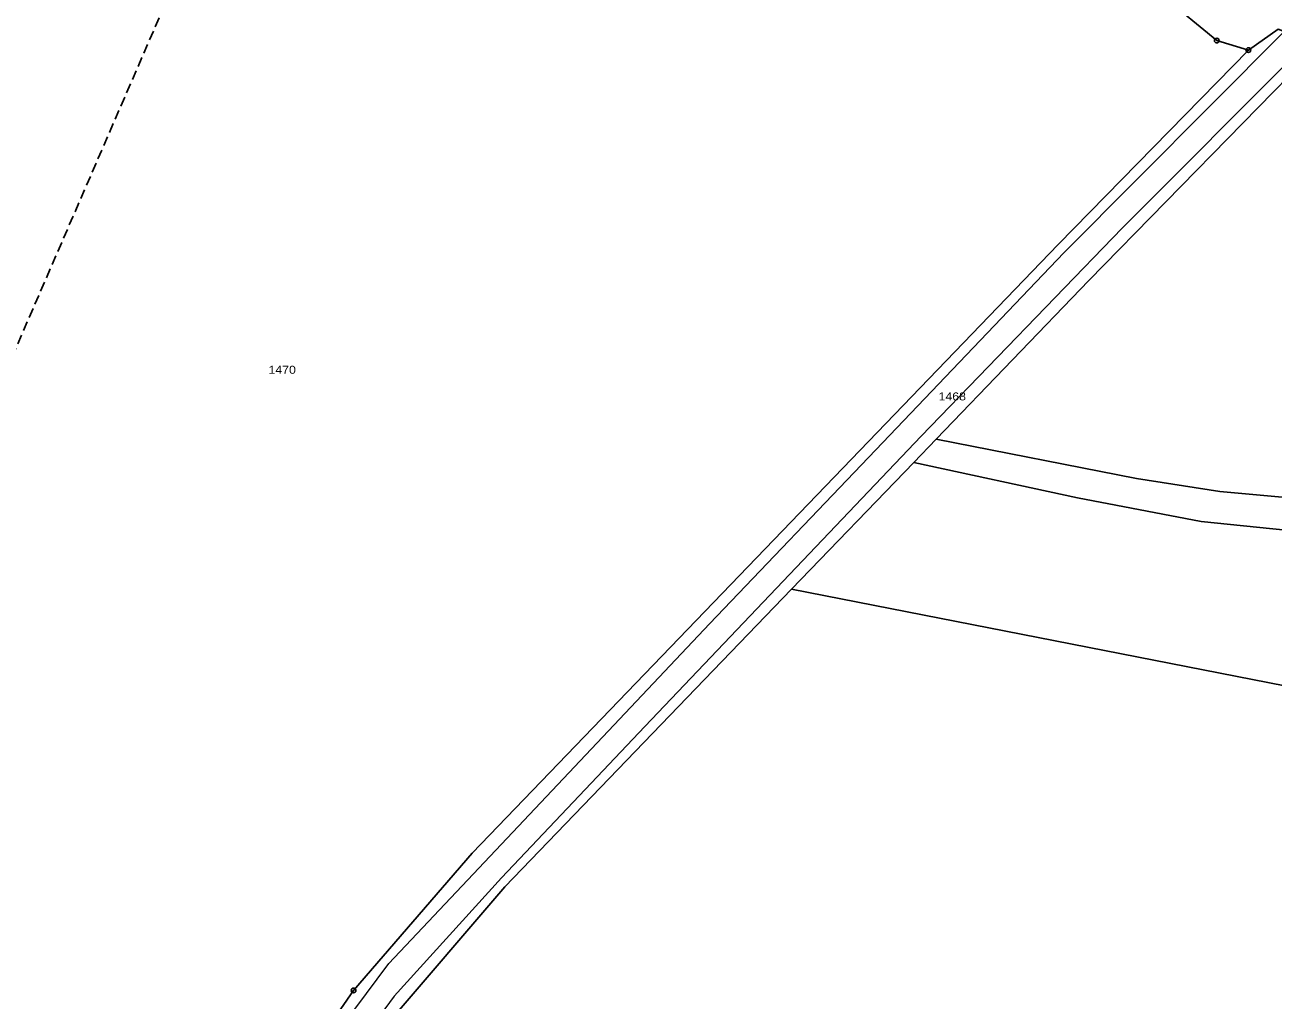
# Model space of a CAD drawing. Extents: x -872229 to -869198, y -1075981 to -1074329.
# Drawn here: x -871472.2 to -871207, y -1075594.7 to -1075387.5 of the extents above; entities that cross this region are included whole.
import ezdxf

# ---------------------------------------------------------------- set-up
doc = ezdxf.new("R2010")
doc.units = 0
doc.header["$LTSCALE"] = 0.68
doc.linetypes.add('MEDIUM_DASHED', pattern=[4.5, 3, -1.5])
for name, color, linetype, lineweight in [('1', 7, 'Continuous', 25), ('4', 7, 'Continuous', 13), ('6', 7, 'Continuous', 25), ('8', 7, 'Continuous', 25)]:
    doc.layers.add(name, color=color, linetype=linetype, lineweight=lineweight)
doc.layers.add('2', color=7, linetype='Continuous')

msp = doc.modelspace()

# ---------------------------------------------------------------- linework, layer by layer
at = {"layer": '1'}
for p, q in [((-871278.54, -1075475.47), (-871283.35, -1075480.46)), ((-871283.35, -1075480.46), (-871309.29, -1075507.4))]:
    msp.add_line(p, q, dxfattribs=at)
for points in [[(-871212.24, -1075392.84), (-871218.94, -1075390.82), (-871230.33, -1075381.38), (-871303.93, -1075360.22), (-871330.24, -1075349.97), (-871352.11, -1075340.43), (-871367.76, -1075336.32)], [(-871197.08, -1075391.62), (-871199.28, -1075390.81), (-871204.62, -1075388.86), (-871205.94, -1075388.38), (-871212.24, -1075392.84)], [(-871212.24, -1075392.84), (-871252.68, -1075434.13), (-871377.15, -1075563.45), (-871402.35, -1075592.63), (-871427.67, -1075629.24), (-871441.61, -1075657.13), (-871468.69, -1075704.44)], [(-871197.08, -1075391.62), (-871246.11, -1075441.8), (-871278.54, -1075475.47)], [(-871278.54, -1075475.47), (-871235.98, -1075483.88), (-871218.31, -1075486.6), (-871156.9, -1075492.22), (-871055.97, -1075499.77), (-870980.4, -1075505.56), (-870961.43, -1075507.47), (-870950.68, -1075443.64)], [(-870962.39, -1075513.2), (-870981.34, -1075511.21), (-871031.87, -1075507.16), (-871090.68, -1075503.32), (-871198.07, -1075495.44), (-871222.24, -1075493), (-871248.51, -1075487.96), (-871283.35, -1075480.46)], [(-871309.29, -1075507.4), (-871370.19, -1075570.62), (-871394.77, -1075599.26), (-871418.31, -1075635.76), (-871432.83, -1075664.02), (-871448.97, -1075707.84), (-871454.61, -1075721.79)], [(-870967.23, -1075543.73), (-871082, -1075537.03), (-871190.36, -1075530.7), (-871309.29, -1075507.4)]]:
    msp.add_lwpolyline(points, dxfattribs=at)
at = {"layer": '4'}
for p, q in [((-871199.28, -1075390.81), (-871239.07, -1075430.66)), ((-871394.86, -1075586.88), (-871326.72, -1075514.76)), ((-871340.49, -1075536.51), (-871370.95, -1075568.72))]:
    msp.add_line(p, q, dxfattribs=at)
for points in [[(-871326.72, -1075514.76), (-871291.4, -1075477.73), (-871251.44, -1075435.93), (-871204.62, -1075388.86)], [(-871239.07, -1075430.66), (-871281.77, -1075474.85), (-871340.49, -1075536.51)], [(-871370.95, -1075568.72), (-871393.73, -1075593.84), (-871411.43, -1075617.88), (-871422.7, -1075636.35)], [(-871423.61, -1075627.58), (-871411.59, -1075609.37), (-871394.86, -1075586.88)]]:
    msp.add_lwpolyline(points, dxfattribs=at)
at = {"layer": '6', "linetype": 'MEDIUM_DASHED'}
msp.add_lwpolyline([(-871440.02, -1075377.58), (-871476.16, -1075460.89), (-871517.14, -1075554.83)], dxfattribs=at)
at = {"layer": '8'}
for centre, radius in [((-871218.94, -1075390.8199), 0.5), ((-871218.94, -1075390.8199), 0.0303), ((-871212.24, -1075392.8399), 0.5), ((-871212.24, -1075392.8399), 0.0303), ((-871402.35, -1075592.6299), 0.5), ((-871402.35, -1075592.6299), 0.0303)]:
    msp.add_circle(centre, radius, dxfattribs=at)

# ---------------------------------------------------------------- texts
at = {"layer": '2', "width": 1.15}
for s, p in [('1470', (-871420.43, -1075461.6)), ('1468', (-871278.06, -1075467.26))]:
    msp.add_text(s, height=1.7, dxfattribs=at).set_placement(p)

doc.saveas('drawing.dxf')
